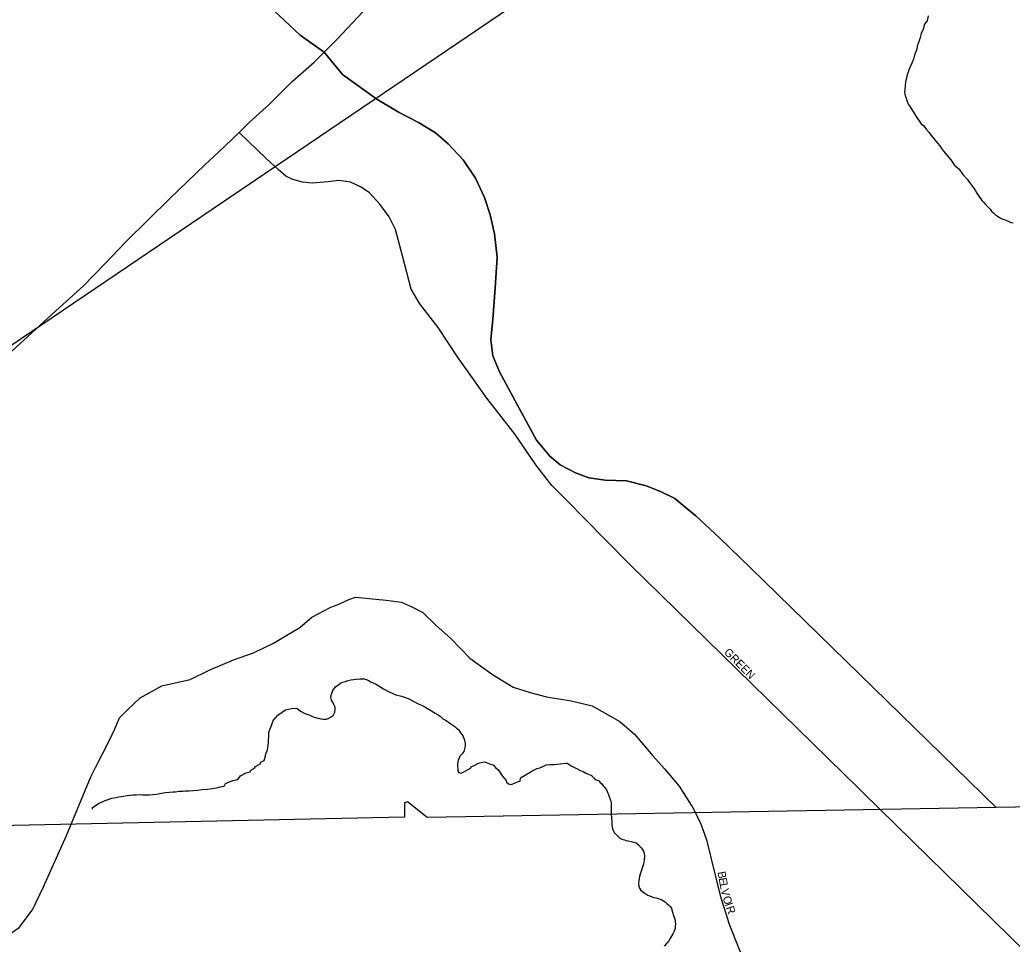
# Model space of a CAD drawing. Extents: x 2139079 to 2262683, y 1235796 to 1334992.
# Drawn here: x 2227269 to 2233466, y 1292167 to 1297941 of the extents above; entities that cross this region are included whole.
import ezdxf

# ---------------------------------------------------------------- set-up
doc = ezdxf.new("R2010")
doc.units = 0
for name, color, linetype in [('GM_X_City_Street', 7, 'Continuous'), ('GM_X_City_Street_Text', 7, 'Continuous'), ('GM_X_Interstate_Route', 7, 'Continuous'), ('GM_X_Minor_River', 7, 'Continuous'), ('GM_X_US_Route', 7, 'Continuous')]:
    doc.layers.add(name, color=color, linetype=linetype)

msp = doc.modelspace()

# ---------------------------------------------------------------- linework, layer by layer
at = {"layer": 'GM_X_City_Street'}
for points in [[(2230763.2, 1294859.1), (2230726.3, 1294896.5), (2230592.6, 1295031.8), (2230490.9, 1295161.7), (2230361.7, 1295351.1), (2230185.4, 1295577.5), (2230002.3, 1295835.8), (2229881.2, 1296019.4), (2229767.1, 1296167.1), (2229712.6, 1296258), (2229659.9, 1296466.8), (2229614.5, 1296631.1), (2229576.1, 1296711.4), (2229518.4, 1296790.1), (2229453.7, 1296860), (2229401.3, 1296896.7), (2229334.9, 1296926.4), (2229261.5, 1296936.9), (2229195.1, 1296929.9), (2229095.5, 1296920.3), (2229035.2, 1296926.4), (2228973.2, 1296943), (2228931.3, 1296963.9), (2228882.3, 1297005.9), (2228808.1, 1297075.8), (2228639.4, 1297238.3)], [(2232535.6, 1293111.5), (2232505.9, 1293140.6), (2231082.7, 1294534.4), (2230786.1, 1294836), (2230763.2, 1294859.1)], [(2227742, 1293271.5), (2227828.5, 1293442.4), (2227862.8, 1293511.6), (2227891.1, 1293580.5), (2227942, 1293630.1), (2228020.2, 1293706.4), (2228156.6, 1293780.2), (2228334, 1293820.9), (2228450.9, 1293878.1), (2228603.6, 1293942.3), (2228728.7, 1293987.7), (2228853.5, 1294047.1), (2228926.6, 1294091.2), (2229017.4, 1294145.7), (2229091.9, 1294209.9), (2229210.6, 1294273.2), (2229256.3, 1294288.5), (2229323.7, 1294320.3), (2229365.4, 1294335.4), (2229492.1, 1294322.7), (2229556.4, 1294316.3), (2229653, 1294302.7), (2229717.9, 1294274.3), (2229786.9, 1294239.9), (2229869.3, 1294157.7), (2229959.6, 1294077.7), (2230079.1, 1293954.3), (2230222.1, 1293851.6), (2230350.5, 1293772.6), (2230455.6, 1293739.2), (2230558.6, 1293711.7), (2230711.6, 1293687.6), (2230842.7, 1293656.8), (2231015.7, 1293558.9), (2231108, 1293478.9), (2231221.8, 1293343.3), (2231296.1, 1293263), (2231387.1, 1293154.9), (2231462.3, 1293035.3), (2231467.3, 1293027.3)], [(2227092.7, 1292187.3), (2227178.6, 1292210.9), (2227265.3, 1292271.4), (2227348.7, 1292382), (2227417.2, 1292524.3), (2227561.3, 1292845.2), (2227712.2, 1293212.5), (2227733.5, 1293254.7), (2227742, 1293271.5)], [(2237139.1, 1283818.1), (2237013.6, 1286565.2), (2236914.8, 1287903.6), (2236898.9, 1288051.7), (2236904.4, 1288071.9), (2236952, 1288095.2), (2237028.2, 1288171.5), (2237100.3, 1288249.6), (2237206.3, 1288419), (2237198.5, 1288487), (2237161.7, 1288590.5), (2237128, 1288653.8), (2237061.6, 1288738.4), (2236872.5, 1288918.2), (2236470.3, 1289275.2), (2235905.5, 1289792.5), (2235277.5, 1290426.7), (2232535.6, 1293111.5)], [(2231467.3, 1293027.3), (2231479.1, 1293008.7), (2231523.7, 1292913.5), (2231558.2, 1292818), (2231643.4, 1292470.8), (2231700.2, 1292291.6), (2231760.2, 1292140.6), (2231823.9, 1292001.7), (2231881.1, 1291884.8), (2231951.7, 1291715.9), (2232108, 1291408.8), (2232285.6, 1291132.3), (2232654.9, 1290654), (2232723.2, 1290571.4), (2232782.8, 1290512.8), (2232848.4, 1290458.2), (2232920.1, 1290397.9), (2233009.9, 1290338), (2233033.1, 1290326.3), (2233036, 1290324.8)]]:
    msp.add_lwpolyline(points, dxfattribs=at)
at = {"layer": 'GM_X_Interstate_Route'}
for points in [[(2228075.8, 1298733.3), (2229020.3, 1297845.9), (2229169, 1297738.8), (2229284.1, 1297598.7), (2229499.3, 1297445.4), (2229638, 1297361.9), (2229758.6, 1297300.4), (2229865.1, 1297234.8), (2229943.6, 1297167.1), (2230038.3, 1297067.3), (2230115.1, 1296951.4), (2230171.9, 1296831.3), (2230206.6, 1296723.2), (2230233.3, 1296605), (2230250.1, 1296458.7), (2230237.2, 1296266), (2230222.3, 1296071.3), (2230211, 1295942.9), (2230223.6, 1295842.6), (2230264.2, 1295742.6), (2230403.9, 1295484.6), (2230497, 1295314.6), (2230579.7, 1295214.8), (2230644.1, 1295161), (2230738.6, 1295111.4), (2230822.9, 1295079.8), (2230925.1, 1295066.3), (2231057.4, 1295061), (2231181.7, 1295029.6), (2231270.1, 1294994), (2231360.5, 1294950.4), (2231434.9, 1294888.7), (2231491.3, 1294842.8), (2231640.3, 1294703.3), (2231831.7, 1294517.8), (2233366.5, 1293020.4), (2229813.4, 1292957.9), (2229690.7, 1293055.5), (2229670.7, 1293049.4), (2229671.2, 1292961.1), (2227031.5, 1292904)], [(2234938.8, 1293048), (2233366.5, 1293020.4), (2231831.7, 1294517.8), (2231640.3, 1294703.3), (2231491.3, 1294842.8), (2231434.9, 1294888.7), (2231360.5, 1294950.4), (2231270.1, 1294994), (2231181.7, 1295029.6), (2231057.4, 1295061), (2230925.1, 1295066.3), (2230822.9, 1295079.8), (2230738.6, 1295111.4), (2230644.1, 1295161), (2230579.7, 1295214.8), (2230497, 1295314.6), (2230403.9, 1295484.6), (2230264.2, 1295742.6), (2230223.6, 1295842.6), (2230211, 1295942.9), (2230222.3, 1296071.3), (2230237.2, 1296266), (2230250.1, 1296458.7), (2230233.3, 1296605), (2230206.6, 1296723.2), (2230171.9, 1296831.3), (2230115.1, 1296951.4), (2230038.3, 1297067.3), (2229943.6, 1297167.1), (2229865.1, 1297234.8), (2229758.6, 1297300.4), (2229638, 1297361.9), (2229499.3, 1297445.4), (2229284.1, 1297598.7), (2229169, 1297738.8), (2229020.3, 1297845.9), (2228075.8, 1298733.3)], [(2234938.8, 1293048), (2233366.5, 1293020.4), (2231831.7, 1294517.8), (2231640.3, 1294703.3), (2231491.3, 1294842.8), (2231434.9, 1294888.7), (2231360.5, 1294950.4), (2231270.1, 1294994), (2231181.7, 1295029.6), (2231057.4, 1295061), (2230925.1, 1295066.3), (2230822.9, 1295079.8), (2230738.6, 1295111.4), (2230644.1, 1295161), (2230579.7, 1295214.8), (2230497, 1295314.6), (2230403.9, 1295484.6), (2230264.2, 1295742.6), (2230223.6, 1295842.6), (2230211, 1295942.9), (2230222.3, 1296071.3), (2230237.2, 1296266), (2230250.1, 1296458.7), (2230233.3, 1296605), (2230206.6, 1296723.2), (2230171.9, 1296831.3), (2230115.1, 1296951.4), (2230038.3, 1297067.3), (2229943.6, 1297167.1), (2229865.1, 1297234.8), (2229758.6, 1297300.4), (2229638, 1297361.9), (2229499.3, 1297445.4), (2229284.1, 1297598.7), (2229169, 1297738.8), (2229020.3, 1297845.9), (2228075.8, 1298733.3)]]:
    msp.add_lwpolyline(points, dxfattribs=at)
at = {"layer": 'GM_X_Minor_River'}
for points in [[(2232942.5, 1297966.5), (2232935.1, 1297934.2), (2232919.4, 1297913.8)], [(2232919.4, 1297913.8), (2232910, 1297883.4), (2232898.6, 1297855.1), (2232891, 1297830.8), (2232885.4, 1297810.6), (2232879.8, 1297792.4), (2232874.1, 1297776.2), (2232870.4, 1297758.1), (2232862.8, 1297737.8), (2232857.1, 1297719.6), (2232849.6, 1297695.4), (2232840.1, 1297671.1), (2232832.4, 1297652.8), (2232826.6, 1297642.7), (2232811.4, 1297598.2), (2232805.9, 1297575.9), (2232800.3, 1297553.7), (2232798.8, 1297529.6), (2232795.3, 1297505.4), (2232793.6, 1297489.3), (2232795.8, 1297477.3), (2232798.1, 1297467.3), (2232802.3, 1297457.3), (2232808.7, 1297437.3), (2232817.2, 1297415.4), (2232829.6, 1297397.6), (2232842.1, 1297377.7), (2232854.5, 1297357.8), (2232867, 1297338), (2232879.4, 1297318.1), (2232889.7, 1297304.3), (2232898, 1297292.4), (2232914.4, 1297278.6), (2232920.6, 1297268.7), (2232928.8, 1297258.8), (2232945.3, 1297239), (2232959.8, 1297219.2), (2232976.2, 1297201.4), (2232990.6, 1297183.6), (2233003, 1297167.8), (2233015.3, 1297154), (2233025.7, 1297138.1), (2233038.1, 1297120.2), (2233083.4, 1297066.9), (2233104.1, 1297035.1), (2233134.8, 1297007.6), (2233159.5, 1296975.9), (2233186.2, 1296946.2), (2233206.9, 1296916.5), (2233225.5, 1296892.8), (2233237.9, 1296872.9), (2233246.2, 1296859), (2233254.6, 1296845.1), (2233262.8, 1296833.2), (2233271.1, 1296823.3), (2233277.3, 1296813.4), (2233287.6, 1296801.5), (2233302, 1296785.7), (2233316.3, 1296771.9), (2233328.6, 1296758.1), (2233336.9, 1296746.2), (2233349.2, 1296736.4), (2233361.4, 1296724.6), (2233373.7, 1296716.8), (2233394, 1296703.1), (2233408.2, 1296695.3), (2233426.4, 1296689.6), (2233442.6, 1296683.9), (2233458.8, 1296676.2), (2233473, 1296672.5)], [(2227722.4, 1293010.9), (2227722.2, 1293021), (2227763.9, 1293047.9), (2227801.7, 1293064.7), (2227827.6, 1293073.2), (2227843.5, 1293079.6), (2227855.5, 1293081.8), (2227867.5, 1293084), (2227887.5, 1293088.4), (2227917.6, 1293091), (2227939.6, 1293095.5), (2227957.6, 1293097.8), (2227975.6, 1293100.2), (2227995.7, 1293100.6), (2228015.8, 1293101), (2228035.9, 1293099.3), (2228060, 1293099.8), (2228080.1, 1293100.2), (2228100.1, 1293102.6), (2228122.1, 1293105), (2228154.2, 1293109.7), (2228178.2, 1293114.1), (2228204.2, 1293116.7), (2228224.2, 1293119.1), (2228242.3, 1293119.4), (2228264.4, 1293121.8), (2228286.4, 1293122.3), (2228304.4, 1293124.6), (2228324.5, 1293125), (2228350.6, 1293127.5), (2228378.7, 1293128.1), (2228406.7, 1293132.6), (2228440.8, 1293135.3), (2228458.8, 1293137.6), (2228472.8, 1293139.9), (2228482.8, 1293142.1), (2228494.8, 1293144.4), (2228508.8, 1293146.7), (2228520.8, 1293148.9), (2228544.8, 1293153.4), (2228554.5, 1293171.6), (2228600.3, 1293188.6), (2228630.3, 1293195.2), (2228647.9, 1293217.7), (2228683.7, 1293236.4), (2228707.7, 1293242.9), (2228711.5, 1293253), (2228735.3, 1293265.6), (2228741.1, 1293277.7), (2228768.9, 1293292.3), (2228776.6, 1293306.5), (2228794.5, 1293314.9), (2228804, 1293341.2), (2228805.7, 1293357.3), (2228813.4, 1293373.6), (2228819, 1293393.7), (2228820.7, 1293409.9), (2228822.4, 1293426), (2228822.1, 1293438), (2228821.9, 1293448.1), (2228823.7, 1293458.1), (2228823.5, 1293468.2), (2228825.3, 1293480.3), (2228825.1, 1293490.3), (2228828.9, 1293502.4), (2228840.3, 1293532.8), (2228851.7, 1293565.2), (2228881.1, 1293597.9), (2228906.9, 1293616.4), (2228928.6, 1293630.9), (2228966.6, 1293639.7), (2228998.7, 1293642.3), (2229021.2, 1293622.7), (2229045.6, 1293609.1), (2229067.8, 1293601.5), (2229079.9, 1293597.7), (2229100.2, 1293588), (2229114.4, 1293582.3), (2229134.5, 1293578.6), (2229148.7, 1293574.9), (2229162.8, 1293573.2), (2229174.8, 1293573.4), (2229184.8, 1293573.6), (2229194.8, 1293575.8), (2229212.6, 1293588.2), (2229226.6, 1293594.5), (2229236.2, 1293616.8), (2229237.8, 1293634.9), (2229237.6, 1293646.9), (2229231.2, 1293664.9), (2229224.9, 1293678.8), (2229216.6, 1293690.7), (2229212.2, 1293708.8), (2229215.8, 1293728.9), (2229223.4, 1293751.1), (2229240.9, 1293775.6), (2229260.7, 1293790.1), (2229272.6, 1293798.3), (2229284.5, 1293804.6), (2229302.5, 1293808.9), (2229318.5, 1293813.3)], [(2229318.5, 1293813.3), (2229336.5, 1293817.6), (2229370.5, 1293822.3), (2229392.6, 1293824.7), (2229406.6, 1293825), (2229420.7, 1293825.3), (2229432.8, 1293819.5), (2229449, 1293813.8), (2229459.2, 1293805.9), (2229475.4, 1293800.2), (2229489.6, 1293792.5), (2229540.4, 1293761.3), (2229558.7, 1293751.6), (2229579, 1293741.9), (2229599.3, 1293732.3), (2229617.5, 1293724.6), (2229635.6, 1293720.9), (2229653.8, 1293715.3), (2229678.1, 1293707.7), (2229694.3, 1293702), (2229710.5, 1293694.3), (2229730.8, 1293682.6), (2229757.2, 1293669), (2229787.6, 1293655.6), (2229816, 1293640), (2229840.4, 1293624.4), (2229862.8, 1293610.8), (2229881.1, 1293599.1), (2229895.3, 1293591.3), (2229911.7, 1293575.6), (2229932, 1293563.9), (2229946.3, 1293554.1), (2229960.5, 1293544.4), (2229972.8, 1293534.6), (2229985, 1293526.8), (2229999.3, 1293515), (2230009.5, 1293507.1), (2230021.9, 1293487.3), (2230032.2, 1293475.4), (2230038.5, 1293463.5), (2230044.8, 1293447.6), (2230049.1, 1293433.6), (2230051.4, 1293421.6), (2230049.7, 1293407.4), (2230047.9, 1293395.4), (2230042.4, 1293371.1), (2230028.7, 1293354.8), (2230016.9, 1293340.5), (2230013.1, 1293328.4), (2230007.3, 1293318.2), (2230001.8, 1293292), (2230004.7, 1293249.9), (2230010.9, 1293239.9), (2230025.1, 1293236.2), (2230043, 1293244.6), (2230064.8, 1293255.1), (2230080.7, 1293265.4), (2230092.5, 1293277.7), (2230106.4, 1293284), (2230134.2, 1293298.6), (2230160.2, 1293303.1), (2230174.2, 1293305.4), (2230192.5, 1293297.7), (2230214.7, 1293290.1), (2230224.8, 1293288.3), (2230239.2, 1293270.5), (2230255.6, 1293256.7), (2230267.9, 1293240.9), (2230282.4, 1293219.1), (2230294.8, 1293203.2), (2230307.1, 1293189.4), (2230309.3, 1293179.4), (2230321.6, 1293167.6), (2230333.8, 1293163.8), (2230343.8, 1293166), (2230361.7, 1293174.4), (2230383.6, 1293182.8), (2230393.6, 1293185), (2230395.2, 1293205.2), (2230456.7, 1293242.5), (2230468.5, 1293250.8), (2230482.5, 1293257.1), (2230498.4, 1293263.4), (2230516.4, 1293267.8), (2230532.3, 1293274.1), (2230556.2, 1293286.6), (2230578.2, 1293289.1), (2230606.3, 1293289.6), (2230644.3, 1293294.4), (2230678.4, 1293297), (2230688.5, 1293297.2), (2230716.9, 1293279.7), (2230737.3, 1293268), (2230755.5, 1293260.3), (2230769.7, 1293252.6), (2230787.9, 1293244.9), (2230804.2, 1293235.2), (2230820.4, 1293229.4), (2230838.6, 1293219.8), (2230857, 1293204), (2230869.3, 1293194.2)], [(2230869.3, 1293194.2), (2230885.5, 1293186.5), (2230893.7, 1293176.6), (2230903.9, 1293168.8), (2230912.2, 1293156.9), (2230920.5, 1293147), (2230932.8, 1293131.2), (2230941.3, 1293111.2), (2230945.5, 1293101.3), (2230951.9, 1293083.3), (2230956.1, 1293071.3), (2230960.4, 1293061.4), (2230962.7, 1293047.3), (2230962.8, 1293037.3), (2230963.1, 1293023.2), (2230961.5, 1293007.1), (2230961.8, 1292993.1), (2230962, 1292979), (2230967, 1292932.9), (2230967.4, 1292912.8), (2230967.7, 1292898.8), (2230969.9, 1292888.8), (2230974.2, 1292876.8), (2230982.5, 1292862.9), (2230996.9, 1292847.1), (2231015.2, 1292831.4), (2231029.5, 1292823.6), (2231045.6, 1292817.9), (2231055.8, 1292814.1), (2231067.9, 1292812.3), (2231088, 1292808.7), (2231104.1, 1292805), (2231118.3, 1292799.2), (2231132.6, 1292787.4), (2231149, 1292769.7), (2231157.3, 1292757.8), (2231163.5, 1292747.8), (2231167.8, 1292735.9), (2231170.3, 1292713.8), (2231168.7, 1292691.7), (2231165.2, 1292667.5), (2231155.7, 1292641.2), (2231150, 1292623), (2231144.4, 1292604.8), (2231138.6, 1292590.7), (2231136.9, 1292576.6), (2231135.2, 1292562.5), (2231133.5, 1292546.3), (2231135.8, 1292530.3), (2231140.2, 1292516.3), (2231146.4, 1292506.4), (2231162.7, 1292492.7), (2231179, 1292480.9), (2231191.2, 1292473.1), (2231229.7, 1292457.8), (2231243.8, 1292456.1), (2231257.9, 1292452.3), (2231268, 1292448.5), (2231278.2, 1292444.7), (2231288.4, 1292436.8), (2231300.6, 1292429), (2231310.8, 1292421.2), (2231321, 1292413.3), (2231333.3, 1292399.5), (2231339.5, 1292389.6), (2231346, 1292367.6), (2231352.5, 1292345.6), (2231358.9, 1292325.7), (2231361.3, 1292307.6), (2231363.6, 1292293.6), (2231361.9, 1292277.5), (2231362.1, 1292265.5), (2231356.5, 1292247.3), (2231346.8, 1292231), (2231333.2, 1292206.6), (2231321.6, 1292188.3), (2231307.8, 1292172), (2231294.1, 1292153.7)]]:
    msp.add_lwpolyline(points, dxfattribs=at)
at = {"layer": 'GM_X_US_Route'}
msp.add_lwpolyline([(2202867.6, 1295541.4), (2210353.6, 1284489.3), (2249318.3, 1310881.6), (2241832.3, 1321933.6)], close=True, dxfattribs=at)
for points in [[(2229183, 1297752.5), (2229251.9, 1297820.1), (2229410.7, 1297992.1), (2229521.9, 1298111.3), (2229670.9, 1298270.9), (2229823.9, 1298428.5), (2230178.2, 1298753.5), (2231308.8, 1299946.9), (2232174.4, 1301030.1), (2232585.7, 1301517.7)], [(2227193.5, 1295848.3), (2227470.2, 1296102.1), (2227667.2, 1296280.1), (2227800.3, 1296417.5), (2227935.3, 1296559.4), (2228205.2, 1296825.9), (2228424.5, 1297036.4), (2228510.1, 1297115.1), (2228639.4, 1297238.3), (2228700.6, 1297300.3), (2228828.2, 1297414.1), (2228969.3, 1297555.5), (2229106.9, 1297676), (2229169, 1297738.8), (2229183, 1297752.5)]]:
    msp.add_lwpolyline(points, dxfattribs=at)

# ---------------------------------------------------------------- texts
at = {"layer": 'GM_X_City_Street_Text'}
for s, rotation, p in [('GREEN', 315, (2231663.2, 1293986.1)), ('B', 280.37653, (2231626.2, 1292617.1)), ('E', 280.35617, (2231633.3, 1292578.2)), ('L', 280.37314, (2231639.7, 1292543.5)), ('V', 282.62788, (2231646.4, 1292506.8)), ('O', 287.98548, (2231657.4, 1292458.9)), ('I', 288.45762, (2231671.1, 1292416.6)), ('R', 288.45799, (2231678.1, 1292395.8))]:
    msp.add_text(s, height=50, rotation=rotation, dxfattribs=at).set_placement(p)

doc.saveas('drawing.dxf')
